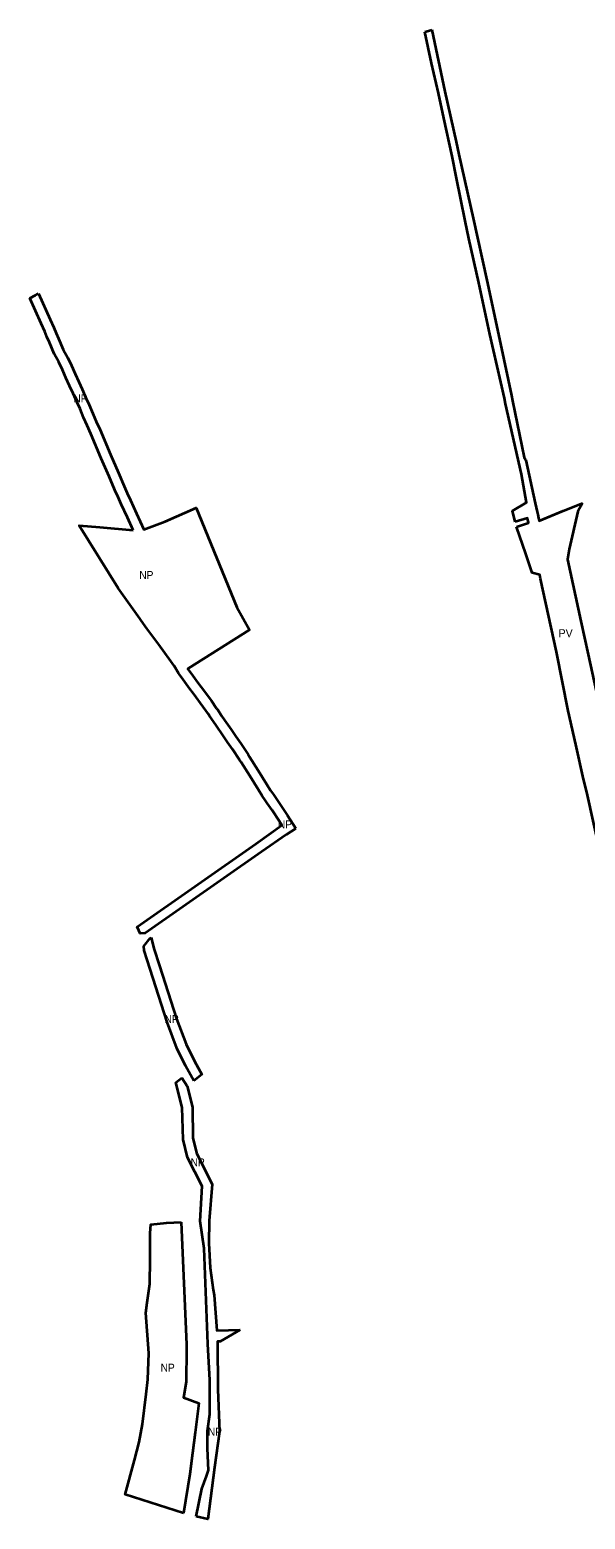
# Model space of a CAD drawing. Extents: x -650971 to -642489, y -1074311 to -1062745.
# Drawn here: x -649558 to -648725, y -1068954 to -1066720 of the extents above; entities that cross this region are included whole.
import ezdxf

# ---------------------------------------------------------------- set-up
doc = ezdxf.new("R2010")
doc.units = 0
doc.header["$LTSCALE"] = 4.8
for name, color, linetype, lineweight in [('15', 7, 'Continuous', 35), ('48', 7, 'Continuous', 35), ('62', 7, 'Continuous', 35)]:
    doc.layers.add(name, color=color, linetype=linetype, lineweight=lineweight)

msp = doc.modelspace()

# ---------------------------------------------------------------- linework, layer by layer
at = {"layer": '15'}
for points in [[(-648965.39, -1066723.15), (-648959.88, -1066721.59), (-648954.86, -1066720.16)], [(-648829.54, -1067458.42), (-648834.01, -1067441.81), (-648812.91, -1067429.16), (-648820.39, -1067386.83), (-648844.16, -1067281.37), (-648845.94, -1067272.85), (-648867.82, -1067176.66), (-648884.26, -1067099.63), (-648899.1, -1067033.34), (-648905.06, -1067006.7), (-648917.76, -1066942.65), (-648924.32, -1066909.55), (-648936.7, -1066852.52), (-648944.75, -1066815.41), (-648955.15, -1066770.11), (-648965.39, -1066723.15)], [(-648954.86, -1066720.16), (-648935.19, -1066812.53), (-648918.27, -1066888.41), (-648914.11, -1066907.05), (-648893.02, -1067002.5), (-648872.31, -1067095.5), (-648851.87, -1067191.04), (-648835.29, -1067268.93), (-648833.66, -1067276.77), (-648816.06, -1067361.71), (-648813.81, -1067365.91)], [(-648813.81, -1067365.91), (-648799.58, -1067430.4), (-648796.8, -1067443.1), (-648795.88, -1067447.21)], [(-648795.88, -1067447.21), (-648794.7, -1067452.46), (-648793.71, -1067456.88), (-648757.97, -1067441.51), (-648728.95, -1067430.33)], [(-648728.95, -1067430.33), (-648735.59, -1067442.88), (-648748.53, -1067499.3), (-648751.29, -1067514.57), (-648731.06, -1067607.06), (-648725.8, -1067632.36), (-648720.1, -1067657.12), (-648708.26, -1067712.07), (-648706.08, -1067723.56)], [(-648827.86, -1067465.86), (-648809.65, -1067459.77), (-648809.97, -1067458.52), (-648811.21, -1067453.52), (-648811.4, -1067452.79), (-648829.54, -1067458.42)], [(-648580.062, -1068590.087), (-648579.97, -1068587.39), (-648566.33, -1068582.22), (-648561.032, -1068578.982), (-648572.95, -1068522.97), (-648573.96, -1068518.34), (-648594.38, -1068425.02), (-648615.87, -1068327.3), (-648634.84, -1068248.76), (-648655.88, -1068153.63), (-648662.71, -1068124.76), (-648677.61, -1068061.74), (-648700.16, -1067963.42), (-648722.09, -1067863.84), (-648727.05, -1067844.33), (-648738.7, -1067792.04), (-648749.97, -1067741.49), (-648767.84, -1067652.98), (-648791.68, -1067543.78), (-648792.97, -1067537.86), (-648804.08, -1067534.88), (-648813.94, -1067506.27), (-648827.86, -1067465.86)]]:
    msp.add_lwpolyline(points, dxfattribs=at)
at = {"layer": '48'}
msp.add_line((-649330.038, -1068291.976), (-649322.18, -1068304.93), dxfattribs=at)
for points in [[(-649558.469, -1067122.73), (-649549.7, -1067118.05), (-649545.203, -1067115.647)], [(-649514.869, -1067218.957), (-649521.663, -1067206.124), (-649529.013, -1067189.389), (-649532.831, -1067180.855), (-649536.075, -1067172.622), (-649541.537, -1067160.722), (-649558.469, -1067122.73)], [(-649545.203, -1067115.647), (-649527.87, -1067154.54), (-649522.27, -1067166.74), (-649519, -1067175.04), (-649515.3, -1067183.31), (-649508.15, -1067199.59), (-649501.49, -1067212.17), (-649495.8, -1067223.89), (-649490.53, -1067236.1), (-649484.93, -1067248.19), (-649479.85, -1067259.45), (-649474.15, -1067272.12), (-649469.21, -1067282.94), (-649463.9, -1067295.72), (-649458.63, -1067307.53), (-649452.95, -1067320.25), (-649437.27, -1067357.17), (-649425.49, -1067384.46), (-649416.8, -1067404.65), (-649412.1, -1067415.11), (-649407.4, -1067425.77), (-649398.28, -1067445.49), (-649387.17, -1067469.893), (-649355.44, -1067457.94), (-649308.75, -1067437.11), (-649247.518, -1067586.255), (-649228.52, -1067620.294), (-649320.47, -1067678.44), (-649321.3, -1067679), (-649316.244, -1067685.919), (-649306.005, -1067699.828), (-649300.936, -1067706.414), (-649285.826, -1067726.842), (-649277.961, -1067738.175), (-649276.322, -1067740.385), (-649270.491, -1067749.283), (-649265.941, -1067755.582), (-649256.092, -1067769.48), (-649249.085, -1067780.02), (-649241.584, -1067790.752), (-649230.661, -1067807.193), (-649228.486, -1067810.867), (-649215.571, -1067831.276), (-649202.625, -1067852), (-649196.89, -1067861.042), (-649192.493, -1067867.375), (-649189.614, -1067871.638), (-649182.332, -1067882.285), (-649171.389, -1067898.756), (-649159.179, -1067918.309)], [(-649472.327, -1067313.644), (-649477.677, -1067301.655), (-649482.963, -1067288.934), (-649487.812, -1067278.312), (-649493.526, -1067265.611), (-649498.572, -1067254.427), (-649504.224, -1067242.225), (-649509.44, -1067230.141), (-649514.869, -1067218.957)], [(-649425.804, -1067421.21), (-649430.531, -1067410.689), (-649439.265, -1067390.397), (-649451.059, -1067363.074), (-649466.703, -1067326.24), (-649472.327, -1067313.644)], [(-649403.34, -1067470.579), (-649411.913, -1067451.746), (-649421.071, -1067431.944), (-649425.804, -1067421.21)], [(-649393.23, -1067603.28), (-649425.69, -1067557.7), (-649484.28, -1067463.88), (-649453.39, -1067466.13), (-649403.34, -1067470.579)], [(-649364.69, -1067641.98), (-649382.53, -1067618.33), (-649391.04, -1067606.27), (-649393.23, -1067603.28)], [(-649333.74, -1067687.4), (-649335.26, -1067685.21), (-649341.81, -1067674.33), (-649349.12, -1067663.84), (-649355.46, -1067654.85), (-649364.69, -1067641.98)], [(-649298.02, -1067735.58), (-649312.91, -1067715.45), (-649317.99, -1067708.85), (-649328.34, -1067694.79), (-649333.74, -1067687.4)], [(-649282.85, -1067757.79), (-649288.63, -1067748.97), (-649290.15, -1067746.92), (-649298.02, -1067735.58)], [(-649253.98, -1067799.2), (-649261.48, -1067788.47), (-649268.46, -1067777.97), (-649278.14, -1067764.31), (-649282.85, -1067757.79)], [(-649228.27, -1067839.26), (-649241.28, -1067818.7), (-649243.37, -1067815.17), (-649253.98, -1067799.2)], [(-649184, -1067906.88), (-649194.77, -1067890.67), (-649202.02, -1067880.07), (-649204.87, -1067875.85), (-649209.39, -1067869.34), (-649215.32, -1067859.99), (-649228.27, -1067839.26)], [(-649219.088, -1067940.964), (-649179.96, -1067913.35), (-649184, -1067906.88)], [(-649159.179, -1067918.309), (-649172.99, -1067927.41), (-649210.54, -1067953.29), (-649385.41, -1068075.32), (-649392.88, -1068075.9), (-649394.83, -1068071.05), (-649397.466, -1068065.442), (-649219.088, -1067940.964)], [(-649312.087, -1068296.653), (-649324.66, -1068274.3), (-649337.52, -1068247.59), (-649352.11, -1068208.65), (-649377.81, -1068129), (-649386.74, -1068101.31), (-649387.46, -1068094.51), (-649377.77, -1068082.44), (-649376.467, -1068081.552)], [(-649376.467, -1068081.552), (-649371.987, -1068098.185), (-649363.534, -1068124.395), (-649337.942, -1068203.713), (-649323.711, -1068241.693), (-649311.352, -1068267.362), (-649300.305, -1068287.002), (-649312.087, -1068296.653)], [(-649302.681, -1068507.363), (-649299.894, -1068454.728), (-649321.727, -1068411.472), (-649328.386, -1068384.468), (-649329.644, -1068336.779), (-649339.046, -1068299.359), (-649330.038, -1068291.976)], [(-649322.18, -1068304.93), (-649314.27, -1068336.41), (-649313.42, -1068382.51), (-649307.57, -1068406.23), (-649284.59, -1068451.76), (-649289.24, -1068506.8), (-649289.74, -1068540.2), (-649287.71, -1068577.14), (-649282.97, -1068610.04), (-649281.4, -1068618.05), (-649277.655, -1068670.983), (-649242.507, -1068669.925)], [(-649384.31, -1068644.92), (-649382.46, -1068629.34), (-649378.08, -1068601.24), (-649377.56, -1068564.89), (-649377.52, -1068525.1), (-649376.77, -1068511.96), (-649353.17, -1068509.48), (-649331.151, -1068508.557)], [(-649331.151, -1068508.557), (-649323.02, -1068692.1), (-649323.1, -1068699.28), (-649323.68, -1068748.06), (-649327.8, -1068771.82), (-649304.66, -1068780.33), (-649310.01, -1068824.2), (-649314.07, -1068855.33), (-649318.13, -1068886.42), (-649327.68, -1068945.23)], [(-649308.65, -1068950), (-649299.91, -1068908.66), (-649293.33, -1068889.65), (-649290.28, -1068880.82), (-649291.87, -1068848.02), (-649291.64, -1068821.88), (-649288.24, -1068796.6), (-649288.19, -1068786.39), (-649287.98, -1068745.74), (-649290.93, -1068690.93), (-649296.55, -1068548.09), (-649302.681, -1068507.363)], [(-649327.68, -1068945.23), (-649327.679, -1068945.222), (-649415.09, -1068917.1), (-649401.31, -1068865.78), (-649394.48, -1068838.89), (-649389.34, -1068811.43), (-649383.78, -1068766.6), (-649381.06, -1068744.69), (-649379.97, -1068704.98), (-649384.31, -1068644.92)], [(-649242.507, -1068669.925), (-649272.755, -1068687.618), (-649276.474, -1068687.673), (-649276.43, -1068688.29), (-649275.96, -1068759.73), (-649273.66, -1068822.58), (-649281.01, -1068876.69), (-649291.32, -1068954.23), (-649308.65, -1068950)]]:
    msp.add_lwpolyline(points, dxfattribs=at)

# ---------------------------------------------------------------- texts
at = {"layer": '62', "width": 0.95}
for p in [(-649492.985, -1067278.967), (-649393.985, -1067543.967), (-649185.985, -1067917.967), (-649355.985, -1068209.967), (-649316.985, -1068424.967), (-649361.985, -1068732.967), (-649290.985, -1068828.967)]:
    msp.add_text('NP', height=12, dxfattribs=at).set_placement(p)
at = {"layer": '62'}
msp.add_text('PV', height=12, dxfattribs=at).set_placement((-648764.767, -1067631.209))

doc.saveas('drawing.dxf')
